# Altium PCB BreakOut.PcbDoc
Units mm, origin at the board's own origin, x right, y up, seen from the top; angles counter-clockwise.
Board outline 150 x 100 mm, 2 copper layers (Top Layer, Bottom Layer); 10 components, 137 nets, 339 pads, 72 vias.
Unrouted connection lines stored in the file: 1.
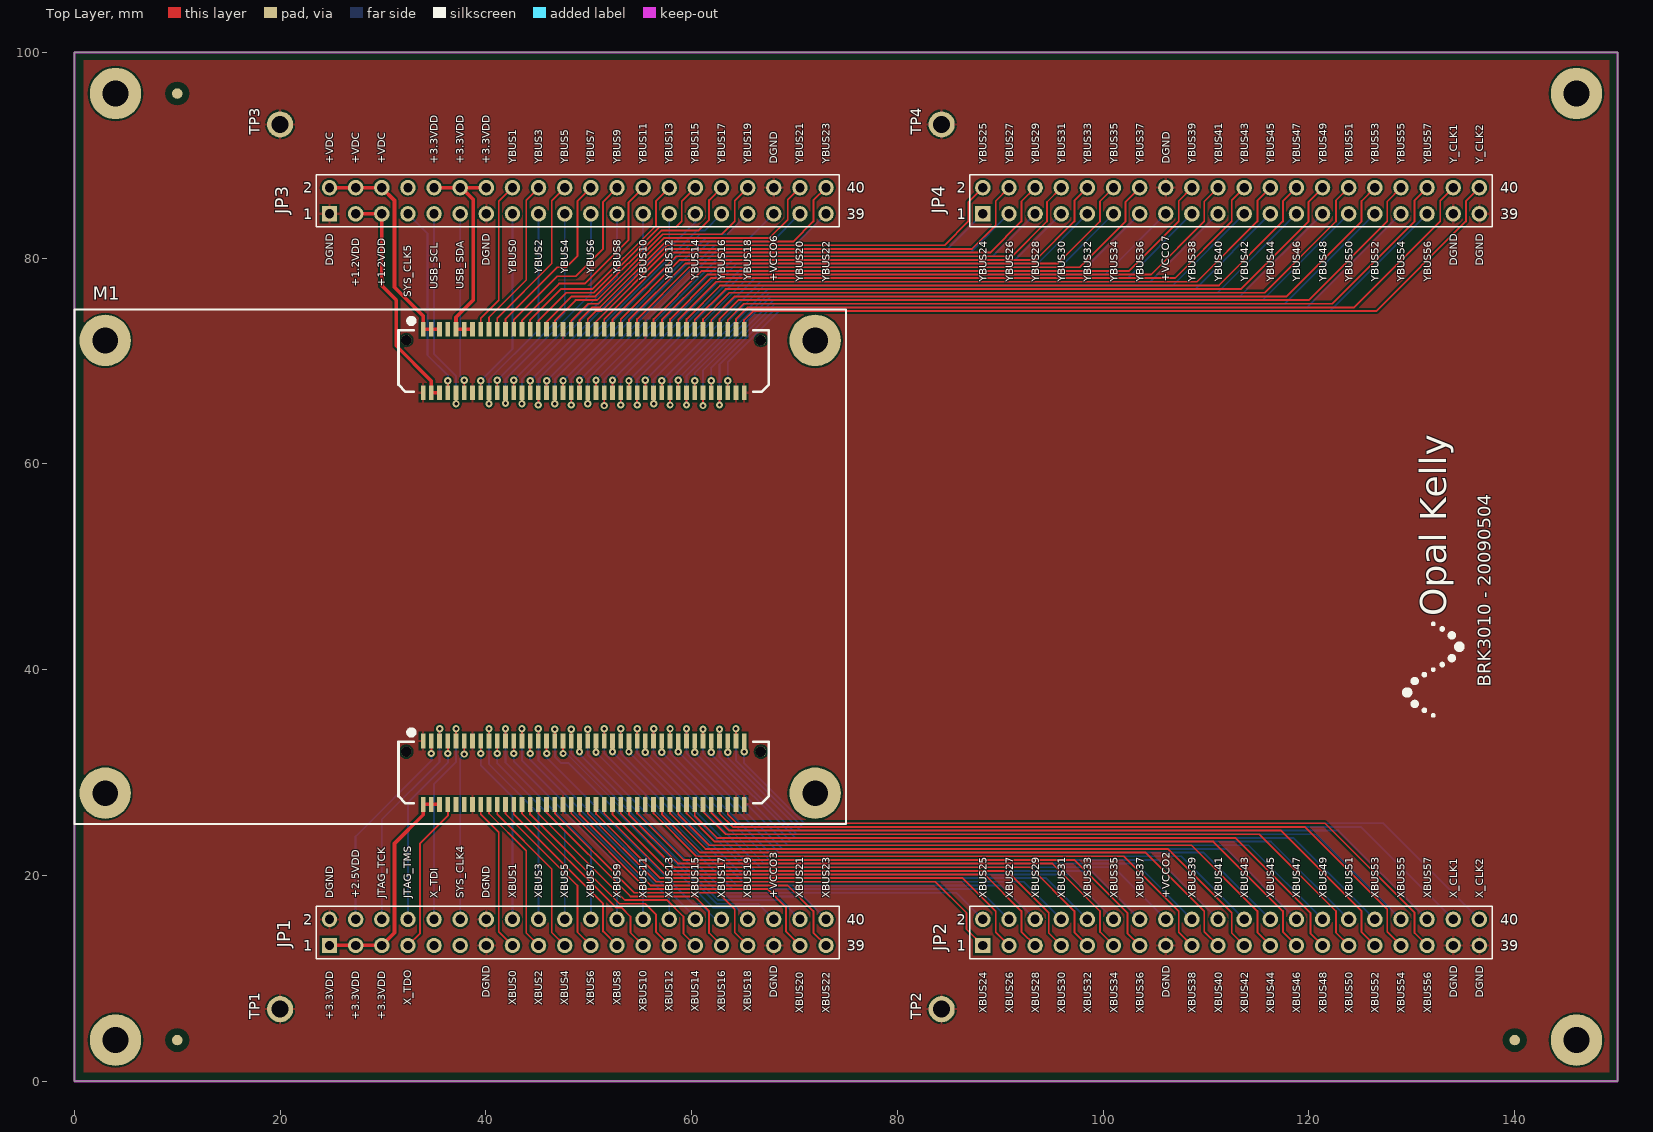
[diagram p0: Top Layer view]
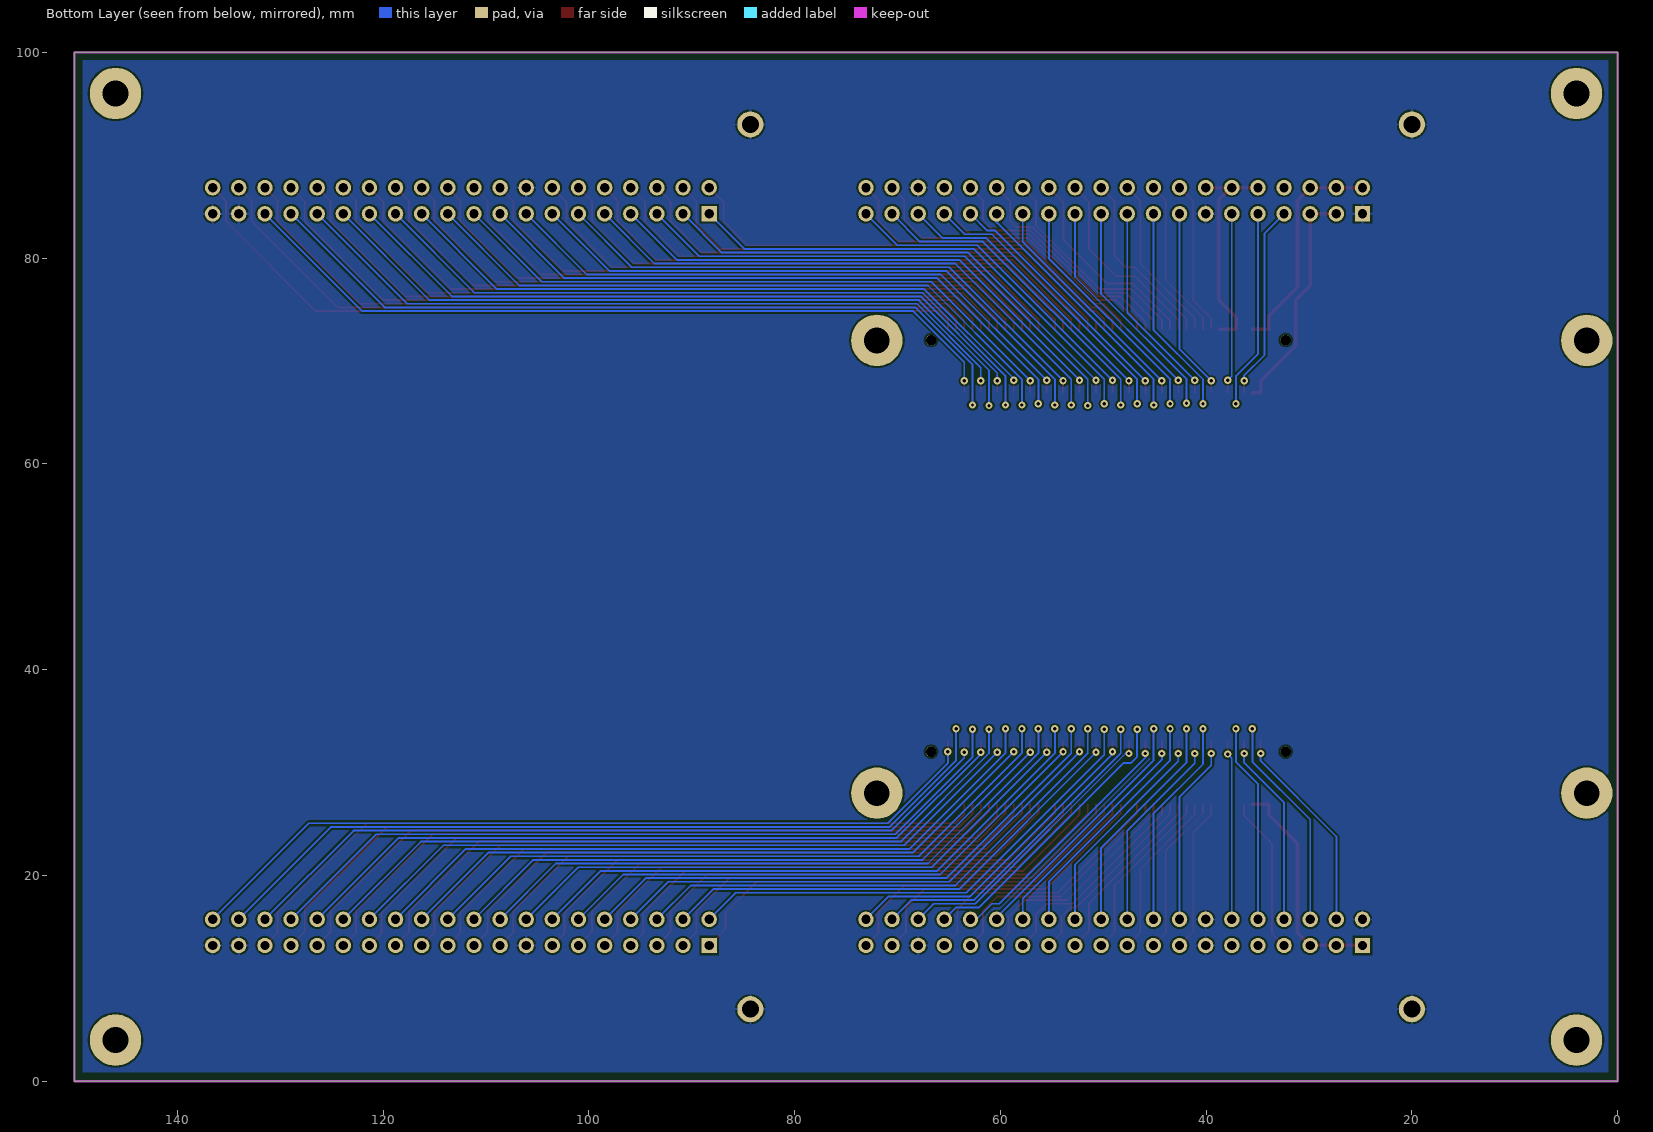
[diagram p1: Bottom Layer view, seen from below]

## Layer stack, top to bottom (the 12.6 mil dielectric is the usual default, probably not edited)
Top Layer: signal copper 0.0356
Dielectric: dielectric 0.32, FR-4, Dk 4.8
Bottom Layer: signal copper 0.0356

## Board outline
0,0 0,100 150,100 150,0

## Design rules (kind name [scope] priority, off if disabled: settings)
Clearance "Polygon Clearance" [InPolygon vs ((Not PadIsPlated) And (HoleSize = 0))] p1: gap=0.635
Clearance [All] p2: gap=0.178
FabricationTestPointUsage TestPointUsage [All] p1: valid=0 allowmultiple=FALSE
FabricationTestpoint Testpoint [All] p1: side=3 testpointundercomponent=TRUE minsize=1.016 maxsize=2.54 preferedsize=1.524 minholesize=0 maxholesize=1.016 preferedholesize=0.813 testpointgrid=0.025 allowsidetop=TRUE allowsidebottom=TRUE usegrid=TRUE gridtolerance=0
HoleSize [All] p1: absolutevalues=TRUE maxlimit=4.064 minlimit=0.33 maxpercent=80.000 minpercent=20.000
PolygonConnect [All] p1: connectstyle=Relief reliefconductorwidth=0.254 reliefentries=4 polygonreliefangle="90 Angle"
RoutingVias [All] p1: holewidth=0.33 width=0.711 viastyle="Through Hole" minholewidth=0.33 minwidth=0.711 maxholewidth=0.711 maxwidth=1.27
SilkscreenOverComponentPads [All] p1: minsilkscreentomaskgap=0.254
SolderMaskExpansion [All] p1: expansion=0.102
Width [All] p1: maxlimit=0.508 minlimit=0.178 preferedwidth=0.178 minimp=50.000000 maximp=50.000000 favimp=50.000000
24 further rules are at their usual default settings.

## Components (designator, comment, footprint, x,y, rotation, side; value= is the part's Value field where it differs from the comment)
JP1 "Header 20X2" HDR2X20 24.8,13.19 r0 top locked
JP2 "Header 20X2" HDR2X20 88.3,13.19 r0 top locked
JP3 "Header 20X2" HDR2X20 24.8,84.31 r0 top locked
JP4 "Header 20X2" HDR2X20 88.3,84.31 r0 top
M1 "XEM3010" XEM3010MODULE 0,25 r0 top locked
TP1 "TESTPOINT" TP_MED#1 20.32,10.668 r0 top
TP2 "TESTPOINT" TP_MED#2 81.072,8.128 r90 top
TP3 "TESTPOINT" TP_MED#3 17.78,93.472 r90 top
TP4 "TESTPOINT" TP_MED#4 81.072,93.472 r90 top
? "OKLOGO" oklogosmall 132.08,35.56 r90 top

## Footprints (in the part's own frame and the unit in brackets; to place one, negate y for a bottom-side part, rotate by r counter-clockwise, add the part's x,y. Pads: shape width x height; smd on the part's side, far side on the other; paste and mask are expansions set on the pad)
HDR2X20 [mm]
  rect 1.5x1.5 hole 0.9: 1(0,0)
  round 1.5 hole 0.9: 2(0,2.54) 3(2.54,0) 4(2.54,2.54) 5(5.08,0) 6(5.08,2.54) 7(7.62,0) 8(7.62,2.54) 9(10.16,0) 10(10.16,2.54) 11(12.7,0) 12(12.7,2.54) 13(15.24,0) 14(15.24,2.54) 15(17.78,0) 16(17.78,2.54) 17(20.32,0) 18(20.32,2.54) 19(22.86,0) 20(22.86,2.54) 21(25.4,0) 22(25.4,2.54) 23(27.94,0) 24(27.94,2.54) 25(30.48,0) 26(30.48,2.54) 27(33.02,0) 28(33.02,2.54) 29(35.56,0) 30(35.56,2.54) 31(38.1,0) 32(38.1,2.54) 33(40.64,0) 34(40.64,2.54) 35(43.18,0) 36(43.18,2.54) 37(45.72,0) 38(45.72,2.54) 39(48.26,0) 40(48.26,2.54)
  silkscreen extent -1.27,-1.27 49.53,3.81
oklogosmall [mm] "Opal Kelly silkscreen logo (100-mil)."
  silkscreen extent -0.11,-2.79 9,2.79
TP_MED#1 [mm] "Testpoint - medium sized"
  round 2.54 hole 1.651: 1(-0.32,-3.668)
TP_MED#2 [mm] "Testpoint - medium sized"
  round 2.54 hole 1.651: 1(-1.128,-3.228)
TP_MED#3 [mm] "Testpoint - medium sized"
  round 2.54 hole 1.651: 1(-0.472,-2.22)
TP_MED#4 [mm] "Testpoint - medium sized"
  round 2.54 hole 1.651: 1(-0.472,-3.228)
XEM3010MODULE [mm] "XEM3010 module footprint"
  round 5 hole 2.5: 0(3,3) 0(3,47) 0(72,3) 0(72,47)
  rect 0.46x1.45 smd: X1(33.9,8.085) X2(33.9,1.915) X3(34.7,8.085) X4(34.7,1.915) X5(35.5,8.085) X6(35.5,1.915) X7(36.3,8.085) X8(36.3,1.915) X9(37.1,8.085) X10(37.1,1.915) X11(37.9,8.085) X12(37.9,1.915) X13(38.7,8.085) X14(38.7,1.915) X15(39.5,8.085) X16(39.5,1.915) X17(40.3,8.085) X18(40.3,1.915) X19(41.1,8.085) X20(41.1,1.915) X21(41.9,8.085) X22(41.9,1.915) X23(42.7,8.085) X24(42.7,1.915) X25(43.5,8.085) X26(43.5,1.915) X27(44.3,8.085) X28(44.3,1.915) X29(45.1,8.085) X30(45.1,1.915) X31(45.9,8.085) X32(45.9,1.915) X33(46.7,8.085) X34(46.7,1.915) X35(47.5,8.085) X36(47.5,1.915) X37(48.3,8.085) X38(48.3,1.915) X39(49.1,8.085) X40(49.1,1.915) X41(49.9,8.085) X42(49.9,1.915) X43(50.7,8.085) X44(50.7,1.915) X45(51.5,8.085) X46(51.5,1.915) X47(52.3,8.085) X48(52.3,1.915) X49(53.1,8.085) X50(53.1,1.915) X51(53.9,8.085) X52(53.9,1.915) X53(54.7,8.085) X54(54.7,1.915) X55(55.5,8.085) X56(55.5,1.915) X57(56.3,8.085) X58(56.3,1.915) X59(57.1,8.085) X60(57.1,1.915) X61(57.9,8.085) X62(57.9,1.915) X63(58.7,8.085) X64(58.7,1.915) X65(59.5,8.085) X66(59.5,1.915) X67(60.3,8.085) X68(60.3,1.915) X69(61.1,8.085) X70(61.1,1.915) X71(61.9,8.085) X72(61.9,1.915) X73(62.7,8.085) X74(62.7,1.915) X75(63.5,8.085) X76(63.5,1.915) X77(64.3,8.085) X78(64.3,1.915) X79(65.1,8.085) X80(65.1,1.915) Y1(33.9,48.085) Y2(33.9,41.915) Y3(34.7,48.085) Y4(34.7,41.915) Y5(35.5,48.085) Y6(35.5,41.915) Y7(36.3,48.085) Y8(36.3,41.915) Y9(37.1,48.085) Y10(37.1,41.915) Y11(37.9,48.085) Y12(37.9,41.915) Y13(38.7,48.085) Y14(38.7,41.915) Y15(39.5,48.085) Y16(39.5,41.915) Y17(40.3,48.085) Y18(40.3,41.915) Y19(41.1,48.085) Y20(41.1,41.915) Y21(41.9,48.085) Y22(41.9,41.915) Y23(42.7,48.085) Y24(42.7,41.915) Y25(43.5,48.085) Y26(43.5,41.915) Y27(44.3,48.085) Y28(44.3,41.915) Y29(45.1,48.085) Y30(45.1,41.915) Y31(45.9,48.085) Y32(45.9,41.915) Y33(46.7,48.085) Y34(46.7,41.915) Y35(47.5,48.085) Y36(47.5,41.915) Y37(48.3,48.085) Y38(48.3,41.915) Y39(49.1,48.085) Y40(49.1,41.915) Y41(49.9,48.085) Y42(49.9,41.915) Y43(50.7,48.085) Y44(50.7,41.915) Y45(51.5,48.085) Y46(51.5,41.915) Y47(52.3,48.085) Y48(52.3,41.915) Y49(53.1,48.085) Y50(53.1,41.915) Y51(53.9,48.085) Y52(53.9,41.915) Y53(54.7,48.085) Y54(54.7,41.915) Y55(55.5,48.085) Y56(55.5,41.915) Y57(56.3,48.085) Y58(56.3,41.915) Y59(57.1,48.085) Y60(57.1,41.915) Y61(57.9,48.085) Y62(57.9,41.915) Y63(58.7,48.085) Y64(58.7,41.915) Y65(59.5,48.085) Y66(59.5,41.915) Y67(60.3,48.085) Y68(60.3,41.915) Y69(61.1,48.085) Y70(61.1,41.915) Y71(61.9,48.085) Y72(61.9,41.915) Y73(62.7,48.085) Y74(62.7,41.915) Y75(63.5,48.085) Y76(63.5,41.915) Y77(64.3,48.085) Y78(64.3,41.915) Y79(65.1,48.085) Y80(65.1,41.915)
  round 1.02 hole 1.02: X81(32.265,7.035) X82(66.735,7.035) Y81(32.265,47.035) Y82(66.735,47.035)
  silkscreen extent 0,0 75,50

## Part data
JP1 JP2 JP3 JP4: "Header, 20-Pin, Dual row"
M1: "XEM3010 module connectors"
TP1 TP2 TP3 TP4: "Testpoint"
?: "Opal Kelly PCB Logo"

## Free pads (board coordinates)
  round 5 hole 2.5: 0(4,4) 0(4,96) 0(146,4) 0(146,96)
  round 1.016 smd mask+0.508: FD0(10,96) FD1(10,4) FD2(140,4)

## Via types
v1: diameter 0.711, hole 0.33, Top Layer to Bottom Layer, tented both sides, 72 vias

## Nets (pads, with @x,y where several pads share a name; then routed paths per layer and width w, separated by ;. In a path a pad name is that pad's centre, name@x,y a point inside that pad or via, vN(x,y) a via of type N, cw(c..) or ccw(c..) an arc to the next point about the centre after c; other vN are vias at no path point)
+1.2VDD: JP3.3 JP3.5 M1.Y4 M1.Y6 | length 22.7
  Top Layer w0.356: JP3.3@27.34,84.3 29.88,84.3 29.88,77.333 31.293,75.921 31.293,71.476 34.7,68.068 M1.Y4 M1.Y6
+2.5VDD: JP1.4 M1.X3 | length 20.4
  Top Layer w0.178: v1(34.7,31.855) M1.X3
  Bottom Layer w0.178: JP1.4@27.34,15.74 27.34,23.784 34.7,31.144 v1(34.7,31.855)
+3.3VDD: JP1.1 JP1.3 JP1.5 JP3.10 JP3.12 JP3.14 M1.X2 M1.X4 M1.X6 M1.Y9 M1.Y11 M1.Y13 | length 43.7
  Top Layer w0.356: JP1.1@24.8,13.2 29.88,13.2 31.115,14.435 31.115,23.114 33.9,25.899 M1.X2 M1.X4 M1.X6 ; JP3.10@34.96,86.84 JP3.14@40.04,86.84 ; JP3.12@37.62,86.84 38.76,85.7 38.76,75.921 37.1,74.26 M1.Y9 M1.Y13
+VCCO2: JP2.16 M1.X55 | length 58.4
  Top Layer w0.178: v1(55.5,31.978) M1.X55
  Bottom Layer w0.178: v1(55.5,31.978) 66.675,20.803 101.017,20.803 JP2.16@106.08,15.74
+VCCO3: JP1.36 M1.X35 | length 28.4
  Top Layer w0.178: v1(47.5,31.854) M1.X35
  Bottom Layer w0.178: v1(47.5,31.854) 47.831,31.854 62.438,17.247 66.473,17.247 JP1.36@67.98,15.74
+VCCO6: JP3.35 M1.Y36 | length 28.4
  Top Layer w0.178: M1.Y36 v1(47.5,68.07)
  Bottom Layer w0.178: v1(47.5,68.07) 61.396,81.966 65.646,81.966 JP3.35@67.98,84.3
+VCCO7: JP4.15 M1.Y56 | length 58.5
  Top Layer w0.178: M1.Y56 v1(55.5,68.124)
  Bottom Layer w0.178: v1(55.5,68.124) 65.786,78.41 100.19,78.41 JP4.15@106.08,84.3
+VDC: JP3.2 JP3.4 JP3.6 M1.Y1 M1.Y3 M1.Y5 | length 22.1
  Top Layer w0.356: JP3.2@24.8,86.84 29.88,86.84 31.115,85.605 31.115,77.165 33.9,74.38 M1.Y1 M1.Y3 M1.Y5
DGND: JP1.2 JP1.13 JP1.14 JP1.35 JP2.15 JP2.37 JP2.39 JP3.1 JP3.13 JP3.36 JP4.16 JP4.37 JP4.39 M1.X1 M1.X13 M1.X14 M1.X36 M1.X56 M1.X78 M1.X80 M1.Y2 M1.Y14 M1.Y35 M1.Y55 M1.Y78 M1.Y80 TP1.1 TP2.1 TP3.1 TP4.1
JTAG_TCK: JP1.6 M1.X5 | length 22
  Top Layer w0.178: M1.X5 v1(35.5,34.255)
  Bottom Layer w0.178: JP1.6@29.88,15.74 29.88,25.435 35.5,31.055 v1(35.5,34.255)
JTAG_TMS: JP1.8 M1.X7 | length 19
  Top Layer w0.178: v1(36.3,31.855) M1.X7
  Bottom Layer w0.178: JP1.8@32.42,15.74 32.42,27.086 36.3,30.966 v1(36.3,31.855)
SYS_CLK4: JP1.12 M1.X11 | length 17.5
  Top Layer w0.178: v1(37.9,31.798) M1.X11
  Bottom Layer w0.178: JP1.12@37.5,15.74 37.5,31.398 v1(37.9,31.798)
SYS_CLK5: JP3.7 M1.Y8 | length 19
  Top Layer w0.178: M1.Y8 v1(36.3,68.069)
  Bottom Layer w0.178: JP3.7@32.42,84.3 34.315,82.405 34.315,70.587 36.3,68.602 v1(36.3,68.069)
USB_SCL: JP3.9 M1.Y10 | length 20.4
  Top Layer w0.178: v1(37.1,65.846) M1.Y10
  Bottom Layer w0.178: JP3.9@34.96,84.3 34.96,70.653 37.1,68.513 v1(37.1,65.846)
USB_SDA: JP3.11 M1.Y12 | length 17.6
  Top Layer w0.178: M1.Y12 v1(37.9,68.126)
  Bottom Layer w0.178: JP3.11@37.5,84.3 37.5,68.526 v1(37.9,68.126)
X_CLK1: JP2.38 M1.X77 | length 80.4
  Top Layer w0.178: M1.X77 v1(64.3,34.252)
  Bottom Layer w0.178: v1(64.3,34.252) 64.3,31.179 70.764,24.714 125.046,24.714 JP2.38@134.02,15.74
X_CLK2: JP2.40 M1.X79 | length 79.9
  Top Layer w0.178: v1(65.1,32.029) M1.X79
  Bottom Layer w0.178: v1(65.1,32.029) 65.1,30.912 70.942,25.07 127.23,25.07 JP2.40@136.56,15.74
X_TDI: JP1.10 M1.X9 | length 20.6
  Top Layer w0.178: M1.X9 v1(37.1,34.255)
  Bottom Layer w0.178: JP1.10@34.96,15.74 34.96,28.915 37.1,31.055 v1(37.1,34.255)
X_TDO: JP1.7 M1.X8 | length 15.3
  Top Layer w0.178: JP1.7@32.42,13.2 33.604,14.384 33.604,23.114 36.3,25.81 M1.X8
XBUS0: JP1.15 M1.X16 | length 15
  Top Layer w0.178: M1.X16 39.5,25.93 41.25,24.181 41.25,14.53 JP1.15@42.58,13.2
XBUS1: JP1.16 M1.X15 | length 18.6
  Top Layer w0.178: v1(39.5,31.855) M1.X15
  Bottom Layer w0.178: v1(39.5,31.855) 39.5,30.731 42.58,27.651 JP1.16@42.58,15.74
XBUS2: JP1.17 M1.X18 | length 15.7
  Top Layer w0.178: M1.X18 40.3,26.019 43.917,22.403 43.917,14.403 JP1.17@45.12,13.2
XBUS3: JP1.18 M1.X17 | length 21.7
  Top Layer w0.178: M1.X17 v1(40.3,34.255)
  Bottom Layer w0.178: v1(40.3,34.255) 40.3,30.82 45.12,26 JP1.18@45.12,15.74
XBUS4: JP1.19 M1.X20 | length 16.4
  Top Layer w0.178: M1.X20 41.1,25.931 46.406,20.625 46.406,14.454 JP1.19@47.66,13.2
XBUS5: JP1.20 M1.X19 | length 20.1
  Top Layer w0.178: v1(41.1,31.854) M1.X19
  Bottom Layer w0.178: v1(41.1,31.854) 41.1,30.909 47.66,24.349 JP1.20@47.66,15.74
XBUS6: JP1.21 M1.X22 | length 17.2
  Top Layer w0.178: M1.X22 41.9,26.02 48.895,19.025 48.895,14.505 JP1.21@50.2,13.2
XBUS7: JP1.22 M1.X21 | length 23.1
  Top Layer w0.178: M1.X21 v1(41.9,34.255)
  Bottom Layer w0.178: v1(41.9,34.255) 41.9,30.998 50.2,22.698 JP1.22@50.2,15.74
XBUS8: JP1.23 M1.X24 | length 17.9
  Top Layer w0.178: M1.X24 42.7,25.931 51.384,17.247 51.384,14.556 JP1.23@52.74,13.2
XBUS9: JP1.24 M1.X23 | length 21.5
  Top Layer w0.178: v1(42.7,31.854) M1.X23
  Bottom Layer w0.178: v1(42.7,31.854) 42.7,31.087 52.74,21.047 JP1.24@52.74,15.74
XBUS10: JP1.25 M1.X26 | length 18.9
  Top Layer w0.178: M1.X26 43.5,26.02 52.629,16.891 53.162,16.891 54.051,16.002 54.051,14.429 JP1.25@55.28,13.2
XBUS11: JP1.26 M1.X25 | length 24.6
  Top Layer w0.178: M1.X25 v1(43.5,34.254)
  Bottom Layer w0.178: v1(43.5,34.254) 43.5,31.176 55.28,19.396 JP1.26@55.28,15.74
XBUS12: JP1.27 M1.X28 | length 20.8
  Top Layer w0.178: M1.X28 44.3,25.931 52.984,17.247 55.474,17.247 56.54,16.18 56.54,14.48 JP1.27@57.82,13.2
XBUS13: JP1.28 M1.X27 | length 22.9
  Top Layer w0.178: v1(44.3,31.854) M1.X27
  Bottom Layer w0.178: v1(44.3,31.854) 44.3,31.265 57.82,17.745 JP1.28@57.82,15.74
XBUS14: JP1.29 M1.X30 | length 22.4
  Top Layer w0.178: M1.X30 45.1,26.02 53.518,17.602 57.607,17.602 59.207,16.002 59.207,14.353 JP1.29@60.36,13.2
XBUS15: JP1.30 M1.X29 | length 26
  Top Layer w0.178: M1.X29 v1(45.1,34.254)
  Bottom Layer w0.178: v1(45.1,34.254) 45.1,31.176 60.36,15.916 JP1.30@60.36,15.74
XBUS16: JP1.31 M1.X32 | length 24.4
  Top Layer w0.178: M1.X32 45.9,26.109 54.051,17.958 60.274,17.958 61.697,16.535 61.697,14.403 JP1.31@62.9,13.2
XBUS17: JP1.32 M1.X31 | length 25.1
  Top Layer w0.178: v1(45.9,31.854) M1.X31
  Bottom Layer w0.178: v1(45.9,31.854) 45.9,31.443 60.096,17.247 60.808,17.247 62.314,15.74 JP1.32@62.9,15.74
XBUS18: JP1.33 M1.X34 | length 26.3
  Top Layer w0.178: M1.X34 46.7,26.02 54.407,18.313 62.586,18.313 64.186,16.713 64.186,14.454 JP1.33@65.44,13.2
XBUS19: JP1.34 M1.X33 | length 29.1
  Top Layer w0.178: M1.X33 v1(46.7,34.199)
  Bottom Layer w0.178: v1(46.7,34.199) 46.7,31.532 47.295,30.937 48.006,30.937 62.052,16.891 64.289,16.891 JP1.34@65.44,15.74
XBUS20: JP1.37 M1.X38 | length 29.8
  Top Layer w0.178: M1.X38 48.3,26.02 55.651,18.669 67.386,18.669 69.164,16.891 69.164,14.556 JP1.37@70.52,13.2
XBUS21: JP1.38 M1.X37 | length 32.3
  Top Layer w0.178: M1.X37 v1(48.3,34.199)
  Bottom Layer w0.178: v1(48.3,34.199) 48.3,31.888 62.586,17.602 68.658,17.602 JP1.38@70.52,15.74
XBUS22: JP1.39 M1.X40 | length 31.5
  Top Layer w0.178: M1.X40 49.1,25.932 56.007,19.025 69.342,19.025 71.831,16.535 71.831,14.429 JP1.39@73.06,13.2
XBUS23: JP1.40 M1.X39 | length 31.9
  Top Layer w0.178: v1(49.1,32.031) M1.X39
  Bottom Layer w0.178: v1(49.1,32.031) 49.1,31.799 62.941,17.958 70.842,17.958 JP1.40@73.06,15.74
XBUS24: JP2.1 M1.X42 | length 45.5
  Top Layer w0.178: M1.X42 49.9,26.021 56.54,19.38 83.688,19.38 86.711,16.358 86.711,14.789 JP2.1@88.3,13.2
XBUS25: JP2.2 M1.X41 | length 48.6
  Top Layer w0.178: M1.X41 v1(49.9,34.199)
  Bottom Layer w0.178: v1(49.9,34.199) 49.9,31.71 63.297,18.313 85.727,18.313 JP2.2@88.3,15.74
XBUS26: JP2.3 M1.X44 | length 47.6
  Top Layer w0.178: M1.X44 50.7,25.986 56.95,19.736 86.355,19.736 89.556,16.535 89.556,14.484 JP2.3@90.84,13.2
XBUS27: JP2.4 M1.X43 | length 48
  Top Layer w0.178: v1(50.7,31.977) M1.X43
  Bottom Layer w0.178: v1(50.7,31.977) 64.008,18.669 87.911,18.669 JP2.4@90.84,15.74
XBUS28: JP2.5 M1.X46 | length 49.3
  Top Layer w0.178: M1.X46 51.5,26.021 57.429,20.091 88.489,20.091 92.045,16.535 92.045,14.535 JP2.5@93.38,13.2
XBUS29: JP2.6 M1.X45 | length 52.1
  Top Layer w0.178: M1.X45 v1(51.5,34.253)
  Bottom Layer w0.178: v1(51.5,34.253) 51.5,31.888 64.364,19.025 90.095,19.025 JP2.6@93.38,15.74
XBUS30: JP2.7 M1.X48 | length 51
  Top Layer w0.178: M1.X48 52.3,25.932 57.785,20.447 90.622,20.447 94.712,16.358 94.712,14.408 JP2.7@95.92,13.2
XBUS31: JP2.8 M1.X47 | length 51.4
  Top Layer w0.178: v1(52.3,32.031) M1.X47
  Bottom Layer w0.178: v1(52.3,32.031) 64.951,19.38 92.28,19.38 JP2.8@95.92,15.74
XBUS32: JP2.9 M1.X50 | length 52.8
  Top Layer w0.178: M1.X50 53.1,26.021 58.318,20.803 92.934,20.803 97.201,16.535 97.201,14.459 JP2.9@98.46,13.2
XBUS33: JP2.10 M1.X49 | length 55.6
  Top Layer w0.178: M1.X49 v1(53.1,34.253)
  Bottom Layer w0.178: v1(53.1,34.253) 53.1,31.888 65.253,19.736 94.464,19.736 JP2.10@98.46,15.74
XBUS34: JP2.11 M1.X52 | length 54.5
  Top Layer w0.178: M1.X52 53.9,25.932 58.674,21.158 95.067,21.158 99.69,16.535 99.69,14.51 JP2.11@101,13.2
XBUS35: JP2.12 M1.X51 | length 54.9
  Top Layer w0.178: v1(53.9,32.031) M1.X51
  Bottom Layer w0.178: v1(53.9,32.031) 65.839,20.091 96.649,20.091 JP2.12@101,15.74
XBUS36: JP2.13 M1.X54 | length 56.2
  Top Layer w0.178: M1.X54 54.7,26.021 59.207,21.514 97.201,21.514 102.357,16.358 102.357,14.383 JP2.13@103.54,13.2
XBUS37: JP2.14 M1.X53 | length 59.1
  Top Layer w0.178: M1.X53 v1(54.7,34.253)
  Bottom Layer w0.178: v1(54.7,34.253) 54.7,31.889 66.142,20.447 98.833,20.447 JP2.14@103.54,15.74
XBUS38: JP2.17 M1.X58 | length 59.7
  Top Layer w0.178: M1.X58 56.3,26.021 60.452,21.869 102.002,21.869 107.336,16.535 107.336,14.484 JP2.17@108.62,13.2
XBUS39: JP2.18 M1.X57 | length 62.5
  Top Layer w0.178: M1.X57 v1(56.3,34.253)
  Bottom Layer w0.178: v1(56.3,34.253) 56.3,31.889 67.031,21.158 103.202,21.158 JP2.18@108.62,15.74
XBUS40: JP2.19 M1.X60 | length 61.5
  Top Layer w0.178: M1.X60 57.1,25.933 60.808,22.225 104.135,22.225 109.825,16.535 109.825,14.535 JP2.19@111.16,13.2
XBUS41: JP2.20 M1.X59 | length 61.9
  Top Layer w0.178: v1(57.1,31.978) M1.X59
  Bottom Layer w0.178: v1(57.1,31.978) 67.564,21.514 105.386,21.514 JP2.20@111.16,15.74
XBUS42: JP2.21 M1.X62 | length 63.1
  Top Layer w0.178: M1.X62 57.9,26.022 61.341,22.581 106.269,22.581 112.492,16.358 112.492,14.408 JP2.21@113.7,13.2
XBUS43: JP2.22 M1.X61 | length 66
  Top Layer w0.178: M1.X61 v1(57.9,34.253)
  Bottom Layer w0.178: v1(57.9,34.253) 57.9,31.889 67.92,21.869 107.571,21.869 JP2.22@113.7,15.74
XBUS44: JP2.23 M1.X64 | length 65
  Top Layer w0.178: M1.X64 58.7,25.933 61.697,22.936 108.58,22.936 114.981,16.535 114.981,14.459 JP2.23@116.24,13.2
XBUS45: JP2.24 M1.X63 | length 65.3
  Top Layer w0.178: v1(58.7,32.03) M1.X63
  Bottom Layer w0.178: v1(58.7,32.03) 68.505,22.225 109.755,22.225 JP2.24@116.24,15.74
XBUS46: JP2.25 M1.X66 | length 66.7
  Top Layer w0.178: M1.X66 59.5,26.022 62.23,23.292 110.714,23.292 117.47,16.535 117.47,14.51 JP2.25@118.78,13.2
XBUS47: JP2.26 M1.X65 | length 69.5
  Top Layer w0.178: M1.X65 v1(59.5,34.252)
  Bottom Layer w0.178: v1(59.5,34.252) 59.5,31.889 68.809,22.581 111.939,22.581 JP2.26@118.78,15.74
XBUS48: JP2.27 M1.X68 | length 68.5
  Top Layer w0.178: M1.X68 60.3,25.807 62.459,23.647 112.847,23.647 120.137,16.358 120.137,14.383 JP2.27@121.32,13.2
XBUS49: JP2.28 M1.X67 | length 68.9
  Top Layer w0.178: v1(60.3,31.978) M1.X67
  Bottom Layer w0.178: v1(60.3,31.978) 69.342,22.936 114.124,22.936 JP2.28@121.32,15.74
XBUS50: JP2.29 M1.X70 | length 70.1
  Top Layer w0.178: M1.X70 61.1,26.2 63.297,24.003 115.159,24.003 122.626,16.535 122.626,14.434 JP2.29@123.86,13.2
XBUS51: JP2.30 M1.X69 | length 72.9
  Top Layer w0.178: M1.X69 v1(61.1,34.201)
  Bottom Layer w0.178: v1(61.1,34.201) 61.1,31.889 69.698,23.292 116.308,23.292 JP2.30@123.86,15.74
XBUS52: JP2.31 M1.X72 | length 71.9
  Top Layer w0.178: M1.X72 61.9,26.111 63.652,24.359 117.292,24.359 125.116,16.535 125.116,14.484 JP2.31@126.4,13.2
XBUS53: JP2.32 M1.X71 | length 72.4
  Top Layer w0.178: v1(61.9,31.978) M1.X71
  Bottom Layer w0.178: v1(61.9,31.978) 61.9,31.801 70.053,23.647 118.493,23.647 JP2.32@126.4,15.74
XBUS54: JP2.33 M1.X74 | length 73.7
  Top Layer w0.178: M1.X74 62.7,26.022 64.008,24.714 119.604,24.714 127.605,16.713 127.605,14.535 JP2.33@128.94,13.2
XBUS55: JP2.34 M1.X73 | length 76.6
  Top Layer w0.178: M1.X73 v1(62.7,34.201)
  Bottom Layer w0.178: v1(62.7,34.201) 62.7,31.534 70.231,24.003 120.677,24.003 JP2.34@128.94,15.74
XBUS56: JP2.35 M1.X76 | length 75.4
  Top Layer w0.178: M1.X76 63.5,25.933 64.364,25.07 121.56,25.07 130.272,16.358 130.272,14.408 JP2.35@131.48,13.2
XBUS57: JP2.36 M1.X75 | length 76.1
  Top Layer w0.178: v1(63.5,31.979) M1.X75
  Bottom Layer w0.178: v1(63.5,31.979) 63.5,31.445 70.587,24.359 122.861,24.359 JP2.36@131.48,15.74
Y_CLK1: JP4.38 M1.Y77 | length 77.2
  Top Layer w0.178: M1.Y77 64.3,74.079 65.43,75.209 124.404,75.209 132.761,83.566 132.761,85.581 JP4.38@134.02,86.84
Y_CLK2: JP4.40 M1.Y79 | length 78.8
  Top Layer w0.178: M1.Y79 65.1,73.99 65.964,74.854 126.538,74.854 135.25,83.566 135.25,85.522 136.56,86.832 JP4.40@136.56,86.84
YBUS0: JP3.15 M1.Y16 | length 18.7
  Top Layer w0.178: M1.Y16 v1(39.5,68.069)
  Bottom Layer w0.178: v1(39.5,68.069) 42.58,71.149 JP3.15@42.58,84.3
YBUS1: JP3.16 M1.Y15 | length 15
  Top Layer w0.178: M1.Y15 39.5,74.171 41.25,75.921 41.25,85.51 JP3.16@42.58,86.84
YBUS2: JP3.17 M1.Y18 | length 21.5
  Top Layer w0.178: v1(40.3,65.847) M1.Y18
  Bottom Layer w0.178: v1(40.3,65.847) 40.3,68.215 45.12,73.035 JP3.17@45.12,84.3
YBUS3: JP3.18 M1.Y17 | length 15.8
  Top Layer w0.178: M1.Y17 40.3,74.26 43.917,77.876 43.917,85.637 JP3.18@45.12,86.84
YBUS4: JP3.19 M1.Y20 | length 20.1
  Top Layer w0.178: M1.Y20 v1(41.1,68.126)
  Bottom Layer w0.178: v1(41.1,68.126) 47.66,74.686 JP3.19@47.66,84.3
YBUS5: JP3.20 M1.Y19 | length 16.5
  Top Layer w0.178: M1.Y19 41.1,74.171 46.406,79.477 46.406,85.586 JP3.20@47.66,86.84
YBUS6: JP3.21 M1.Y22 | length 22.8
  Top Layer w0.178: v1(41.9,65.903) M1.Y22
  Bottom Layer w0.178: v1(41.9,65.903) 41.9,68.214 50.2,76.514 JP3.21@50.2,84.3
YBUS7: JP3.22 M1.Y21 | length 17.7
  Top Layer w0.178: M1.Y21 41.9,74.082 46.939,79.121 47.828,79.121 48.895,80.188 48.895,85.535 JP3.22@50.2,86.84
YBUS8: JP3.23 M1.Y24 | length 21.5
  Top Layer w0.178: M1.Y24 v1(42.7,68.125)
  Bottom Layer w0.178: v1(42.7,68.125) 52.74,78.165 JP3.23@52.74,84.3
YBUS9: JP3.24 M1.Y23 | length 19
  Top Layer w0.178: M1.Y23 42.7,73.993 46.939,78.232 48.717,78.232 51.384,80.899 51.384,85.484 JP3.24@52.74,86.84
YBUS10: JP3.25 M1.Y26 | length 24.4
  Top Layer w0.178: v1(43.5,65.847) M1.Y26
  Bottom Layer w0.178: v1(43.5,65.847) 43.5,68.214 55.28,79.994 JP3.25@55.28,84.3
YBUS11: JP3.26 M1.Y25 | length 20.1
  Top Layer w0.178: M1.Y25 43.5,73.904 47.117,77.521 49.606,77.521 53.873,81.788 53.873,85.433 JP3.26@55.28,86.84
YBUS12: JP3.27 M1.Y28 | length 23
  Top Layer w0.178: M1.Y28 v1(44.3,68.07)
  Bottom Layer w0.178: v1(44.3,68.07) 57.82,81.59 JP3.27@57.82,84.3
YBUS13: JP3.28 M1.Y27 | length 21.1
  Top Layer w0.178: M1.Y27 44.3,73.993 47.295,76.987 50.353,76.987 56.54,83.175 56.54,85.56 JP3.28@57.82,86.84
YBUS14: JP3.29 M1.Y30 | length 26.1
  Top Layer w0.178: v1(45.1,65.725) M1.Y30
  Bottom Layer w0.178: v1(45.1,65.725) 45.1,68.214 60.36,83.474 JP3.29@60.36,84.3
YBUS15: JP3.30 M1.Y29 | length 22.6
  Top Layer w0.178: M1.Y29 45.1,73.904 47.828,76.632 50.5,76.632 56.901,83.033 58.496,83.033 59.03,83.566 59.03,85.51 JP3.30@60.36,86.84
YBUS16: JP3.31 M1.Y32 | length 24.9
  Top Layer w0.178: M1.Y32 v1(45.9,68.07)
  Bottom Layer w0.178: v1(45.9,68.07) 60.507,82.677 61.277,82.677 JP3.31@62.9,84.3
YBUS17: JP3.32 M1.Y31 | length 24.2
  Top Layer w0.178: M1.Y31 45.9,73.815 48.362,76.276 50.648,76.276 57.049,82.677 60.63,82.677 61.697,83.744 61.697,85.637 JP3.32@62.9,86.84
YBUS18: JP3.33 M1.Y34 | length 28.8
  Top Layer w0.178: v1(46.7,65.847) M1.Y34
  Bottom Layer w0.178: v1(46.7,65.847) 46.7,68.214 60.808,82.321 63.461,82.321 JP3.33@65.44,84.3
YBUS19: JP3.34 M1.Y33 | length 26.1
  Top Layer w0.178: M1.Y33 46.7,73.903 48.717,75.921 50.795,75.921 57.196,82.321 62.941,82.321 64.186,83.566 64.186,85.586 JP3.34@65.44,86.84
YBUS20: JP3.37 M1.Y38 | length 32.6
  Top Layer w0.178: v1(48.3,65.724) M1.Y38
  Bottom Layer w0.178: v1(48.3,65.724) 48.3,68.214 61.697,81.61 67.83,81.61 JP3.37@70.52,84.3
YBUS21: JP3.38 M1.Y37 | length 29.5
  Top Layer w0.178: M1.Y37 48.3,73.903 49.962,75.565 50.942,75.565 57.343,81.966 67.564,81.966 69.342,83.744 69.342,85.662 JP3.38@70.52,86.84
YBUS22: JP3.39 M1.Y40 | length 31.9
  Top Layer w0.178: M1.Y40 v1(49.1,68.125)
  Bottom Layer w0.178: v1(49.1,68.125) 62.23,81.255 70.015,81.255 JP3.39@73.06,84.3
YBUS23: JP3.40 M1.Y39 | length 31.4
  Top Layer w0.178: M1.Y39 49.1,73.992 50.317,75.209 51.09,75.209 57.49,81.61 69.875,81.61 71.831,83.566 71.831,85.611 JP3.40@73.06,86.84
YBUS24: JP4.1 M1.Y42 | length 48.5
  Top Layer w0.178: v1(49.9,65.848) M1.Y42
  Bottom Layer w0.178: v1(49.9,65.848) 49.9,68.213 62.586,80.899 84.899,80.899 JP4.1@88.3,84.3
YBUS25: JP4.2 M1.Y41 | length 45.8
  Top Layer w0.178: M1.Y41 49.9,74.081 50.673,74.854 51.237,74.854 57.638,81.255 84.577,81.255 86.889,83.566 86.889,85.429 JP4.2@88.3,86.84
YBUS26: JP4.3 M1.Y44 | length 48
  Top Layer w0.178: M1.Y44 v1(50.7,68.124)
  Bottom Layer w0.178: v1(50.7,68.124) 63.119,80.543 87.083,80.543 JP4.3@90.84,84.3
YBUS27: JP4.4 M1.Y43 | length 47.6
  Top Layer w0.178: M1.Y43 50.7,73.814 57.785,80.899 87.244,80.899 89.556,83.21 89.556,85.556 JP4.4@90.84,86.84
YBUS28: JP4.5 M1.Y46 | length 52.3
  Top Layer w0.178: v1(51.5,65.67) M1.Y46
  Bottom Layer w0.178: v1(51.5,65.67) 51.5,68.213 63.475,80.188 89.268,80.188 JP4.5@93.38,84.3
YBUS29: JP4.6 M1.Y45 | length 49.3
  Top Layer w0.178: M1.Y45 51.5,74.081 57.963,80.543 89.022,80.543 92.045,83.566 92.045,85.505 JP4.6@93.38,86.84
YBUS30: JP4.7 M1.Y48 | length 51.5
  Top Layer w0.178: M1.Y48 v1(52.3,68.124)
  Bottom Layer w0.178: v1(52.3,68.124) 64.008,79.832 91.452,79.832 JP4.7@95.92,84.3
YBUS31: JP4.8 M1.Y47 | length 51
  Top Layer w0.178: M1.Y47 52.3,73.992 58.496,80.188 91.156,80.188 94.534,83.566 94.534,85.454 JP4.8@95.92,86.84
YBUS32: JP4.9 M1.Y50 | length 55.7
  Top Layer w0.178: v1(53.1,65.724) M1.Y50
  Bottom Layer w0.178: v1(53.1,65.724) 53.1,68.213 64.364,79.477 93.637,79.477 JP4.9@98.46,84.3
YBUS33: JP4.10 M1.Y49 | length 52.8
  Top Layer w0.178: M1.Y49 53.1,74.08 58.852,79.832 93.467,79.832 97.201,83.566 97.201,85.581 JP4.10@98.46,86.84
YBUS34: JP4.11 M1.Y52 | length 55
  Top Layer w0.178: M1.Y52 v1(53.9,68.071)
  Bottom Layer w0.178: v1(53.9,68.071) 64.95,79.121 95.821,79.121 JP4.11@101,84.3
YBUS35: JP4.12 M1.Y51 | length 54.5
  Top Layer w0.178: M1.Y51 53.9,73.991 59.385,79.477 95.601,79.477 99.69,83.566 99.69,85.53 JP4.12@101,86.84
YBUS36: JP4.13 M1.Y54 | length 59.2
  Top Layer w0.178: v1(54.7,65.724) M1.Y54
  Bottom Layer w0.178: v1(54.7,65.724) 54.7,68.213 65.253,78.765 98.005,78.765 JP4.13@103.54,84.3
YBUS37: JP4.14 M1.Y53 | length 56.2
  Top Layer w0.178: M1.Y53 54.7,74.08 59.741,79.121 97.734,79.121 102.179,83.566 102.179,85.479 JP4.14@103.54,86.84
YBUS38: JP4.17 M1.Y58 | length 62.4
  Top Layer w0.178: v1(56.3,65.849) M1.Y58
  Bottom Layer w0.178: v1(56.3,65.849) 56.3,68.213 66.142,78.054 102.374,78.054 JP4.17@108.62,84.3
YBUS39: JP4.18 M1.Y57 | length 59.8
  Top Layer w0.178: M1.Y57 56.3,74.08 60.985,78.765 102.535,78.765 107.336,83.566 107.336,85.556 JP4.18@108.62,86.84
YBUS40: JP4.19 M1.Y60 | length 61.9
  Top Layer w0.178: M1.Y60 v1(57.1,68.071)
  Bottom Layer w0.178: v1(57.1,68.071) 66.727,77.699 104.559,77.699 JP4.19@111.16,84.3
YBUS41: JP4.20 M1.Y59 | length 61.4
  Top Layer w0.178: M1.Y59 57.1,73.991 61.519,78.41 104.669,78.41 109.825,83.566 109.825,85.505 JP4.20@111.16,86.84
YBUS42: JP4.21 M1.Y62 | length 66.1
  Top Layer w0.178: v1(57.9,65.723) M1.Y62
  Bottom Layer w0.178: v1(57.9,65.723) 57.9,68.212 67.031,77.343 106.743,77.343 JP4.21@113.7,84.3
YBUS43: JP4.22 M1.Y61 | length 63.3
  Top Layer w0.178: M1.Y61 57.9,74.08 61.874,78.054 106.98,78.054 112.492,83.566 112.492,85.632 JP4.22@113.7,86.84
YBUS44: JP4.23 M1.Y64 | length 65.6
  Top Layer w0.178: M1.Y64 v1(58.7,68.123)
  Bottom Layer w0.178: v1(58.7,68.123) 58.7,68.301 67.386,76.987 108.927,76.987 JP4.23@116.24,84.3
YBUS45: JP4.24 M1.Y63 | length 64.9
  Top Layer w0.178: M1.Y63 58.7,73.991 62.408,77.699 109.114,77.699 114.981,83.566 114.981,85.581 JP4.24@116.24,86.84
YBUS46: JP4.25 M1.Y66 | length 69.8
  Top Layer w0.178: v1(59.5,65.723) M1.Y66
  Bottom Layer w0.178: v1(59.5,65.723) 59.5,68.568 67.564,76.632 111.112,76.632 JP4.25@118.78,84.3
YBUS47: JP4.26 M1.Y65 | length 66.7
  Top Layer w0.178: M1.Y65 59.5,74.08 62.763,77.343 111.247,77.343 117.47,83.566 117.47,85.53 JP4.26@118.78,86.84
YBUS48: JP4.27 M1.Y68 | length 69.3
  Top Layer w0.178: M1.Y68 v1(60.3,68.072)
  Bottom Layer w0.178: v1(60.3,68.072) 60.3,68.834 67.742,76.276 113.296,76.276 JP4.27@121.32,84.3
YBUS49: JP4.28 M1.Y67 | length 68.4
  Top Layer w0.178: M1.Y67 60.3,73.991 63.297,76.987 113.381,76.987 119.959,83.566 119.959,85.479 JP4.28@121.32,86.84
YBUS50: JP4.29 M1.Y70 | length 73.7
  Top Layer w0.178: v1(61.1,65.671) M1.Y70
  Bottom Layer w0.178: v1(61.1,65.671) 61.1,69.101 67.92,75.921 115.481,75.921 JP4.29@123.86,84.3
YBUS51: JP4.30 M1.Y69 | length 70.2
  Top Layer w0.178: M1.Y69 61.1,74.079 63.652,76.632 115.692,76.632 122.626,83.566 122.626,85.606 JP4.30@123.86,86.84
YBUS52: JP4.31 M1.Y72 | length 73.1
  Top Layer w0.178: M1.Y72 v1(61.9,68.072)
  Bottom Layer w0.178: v1(61.9,68.072) 61.9,69.368 68.097,75.565 117.665,75.565 JP4.31@126.4,84.3
YBUS53: JP4.32 M1.Y71 | length 71.9
  Top Layer w0.178: M1.Y71 61.9,73.99 64.186,76.276 117.826,76.276 125.116,83.566 125.116,85.556 JP4.32@126.4,86.84
YBUS54: JP4.33 M1.Y74 | length 77.4
  Top Layer w0.178: v1(62.7,65.723) M1.Y74
  Bottom Layer w0.178: v1(62.7,65.723) 62.7,69.634 68.275,75.209 119.849,75.209 JP4.33@128.94,84.3
YBUS55: JP4.34 M1.Y73 | length 73.7
  Top Layer w0.178: M1.Y73 62.7,74.079 64.541,75.921 119.959,75.921 127.605,83.566 127.605,85.505 JP4.34@128.94,86.84
YBUS56: JP4.35 M1.Y76 | length 76.9
  Top Layer w0.178: M1.Y76 v1(63.5,68.072)
  Bottom Layer w0.178: v1(63.5,68.072) 63.5,69.901 68.453,74.854 122.034,74.854 JP4.35@131.48,84.3
YBUS57: JP4.36 M1.Y75 | length 75.4
  Top Layer w0.178: M1.Y75 63.5,73.99 65.075,75.565 122.271,75.565 130.272,83.566 130.272,85.632 JP4.36@131.48,86.84
pads on no net: JP1.9 JP1.11 JP3.8 M1.0 M1.X10 M1.X12 M1.X81 M1.X82 M1.Y7 M1.Y81 M1.Y82

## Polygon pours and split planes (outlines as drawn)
DGND on Top Layer "Top Layer-DGND" (solid, remove dead copper, pour order 1000): 0.889,0.889 149.174,0.889 149.174,99.212 0.889,99.212
DGND on Bottom Layer "Bot Layer-DGND" (solid, remove dead copper, pour order 1000): 0.889,0.889 149.174,0.889 149.174,99.212 0.889,99.212

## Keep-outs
Keep-Out Layer:
  the board outline again, w0.203

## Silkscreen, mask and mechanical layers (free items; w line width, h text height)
Top Overlay:
  text "+VDC" at 25.146,89.154 h0.76 r90
  text "+VDC" at 27.686,89.154 h0.76 r90
  text "+VDC" at 30.226,89.154 h0.76 r90
  text "+3.3VDD" at 35.306,89.154 h0.76 r90
  text "+3.3VDD" at 37.846,89.154 h0.76 r90
  text "+3.3VDD" at 40.386,89.154 h0.76 r90
  text "YBUS1" at 42.926,89.154 h0.76 r90
  text "YBUS3" at 45.466,89.154 h0.76 r90
  text "YBUS5" at 48.006,89.154 h0.76 r90
  text "YBUS7" at 50.546,89.154 h0.76 r90
  text "YBUS9" at 53.086,89.154 h0.76 r90
  text "YBUS11" at 55.626,89.154 h0.76 r90
  text "YBUS13" at 58.166,89.154 h0.76 r90
  text "YBUS15" at 60.706,89.154 h0.76 r90
  text "YBUS17" at 63.246,89.154 h0.76 r90
  text "YBUS19" at 65.786,89.154 h0.76 r90
  text "DGND" at 68.326,89.154 h0.76 r90
  text "YBUS21" at 70.866,89.154 h0.76 r90
  text "YBUS23" at 73.406,89.154 h0.76 r90
  text "YBUS25" at 88.692,89.154 h0.76 r90
  text "YBUS27" at 91.232,89.154 h0.76 r90
  text "YBUS29" at 93.772,89.154 h0.76 r90
  text "YBUS31" at 96.312,89.154 h0.76 r90
  text "YBUS33" at 98.852,89.154 h0.76 r90
  text "YBUS35" at 101.392,89.154 h0.76 r90
  text "YBUS37" at 103.932,89.154 h0.76 r90
  text "DGND" at 106.472,89.154 h0.76 r90
  text "YBUS39" at 109.012,89.154 h0.76 r90
  text "YBUS41" at 111.552,89.154 h0.76 r90
  text "YBUS43" at 114.092,89.154 h0.76 r90
  text "YBUS45" at 116.632,89.154 h0.76 r90
  text "YBUS47" at 119.172,89.154 h0.76 r90
  text "YBUS49" at 121.712,89.154 h0.76 r90
  text "YBUS51" at 124.252,89.154 h0.76 r90
  text "YBUS53" at 126.792,89.154 h0.76 r90
  text "YBUS55" at 129.332,89.154 h0.76 r90
  text "YBUS57" at 131.872,89.154 h0.76 r90
  text "Y_CLK1" at 134.412,89.154 h0.76 r90
  text "Y_CLK2" at 136.952,89.154 h0.76 r90
  text "DGND" at 25.146,79.247 h0.76 r90
  text "DGND" at 40.386,79.247 h0.76 r90
  text "DGND" at 134.412,79.247 h0.76 r90
  text "DGND" at 136.952,79.247 h0.76 r90
  text "YBUS0" at 42.926,78.486 h0.76 r90
  text "YBUS2" at 45.466,78.486 h0.76 r90
  text "YBUS4" at 48.006,78.486 h0.76 r90
  text "YBUS6" at 50.546,78.486 h0.76 r90
  text "YBUS8" at 53.086,78.486 h0.76 r90
  text "YBUS10" at 55.626,77.851 h0.76 r90
  text "YBUS12" at 58.166,77.851 h0.76 r90
  text "YBUS14" at 60.706,77.851 h0.76 r90
  text "YBUS16" at 63.246,77.851 h0.76 r90
  text "YBUS18" at 65.786,77.851 h0.76 r90
  text "YBUS20" at 70.866,77.724 h0.76 r90
  text "YBUS22" at 73.406,77.724 h0.76 r90
  text "YBUS24" at 88.692,77.724 h0.76 r90
  text "YBUS26" at 91.232,77.724 h0.76 r90
  text "YBUS28" at 93.772,77.724 h0.76 r90
  text "YBUS30" at 96.312,77.724 h0.76 r90
  text "YBUS32" at 98.852,77.724 h0.76 r90
  text "YBUS34" at 101.392,77.724 h0.76 r90
  text "YBUS36" at 103.932,77.724 h0.76 r90
  text "+VCCO7" at 106.426,77.724 h0.76 r90
  text "YBUS38" at 109.012,77.724 h0.76 r90
  text "YBUS40" at 111.552,77.724 h0.76 r90
  text "YBUS42" at 114.092,77.724 h0.76 r90
  text "YBUS44" at 116.632,77.724 h0.76 r90
  text "YBUS46" at 119.172,77.724 h0.76 r90
  text "YBUS48" at 121.712,77.724 h0.76 r90
  text "YBUS50" at 124.252,77.724 h0.76 r90
  text "YBUS52" at 126.792,77.724 h0.76 r90
  text "YBUS54" at 129.332,77.724 h0.76 r90
  text "YBUS56" at 131.872,77.724 h0.76 r90
  text "+VCCO6" at 68.326,77.699 h0.76 r90
  text "+1.2VDD" at 27.686,77.216 h0.76 r90
  text "+1.2VDD" at 30.226,77.216 h0.76 r90
  text "USB_SCL" at 35.306,76.962 h0.76 r90
  text "USB_SDA" at 37.846,76.962 h0.76 r90
  text "SYS_CLK5" at 32.766,76.2 h0.76 r90
  text "BRK3010 - 20090504" at 137.668,38.354 h1.27 r90
  text "DGND" at 25.146,17.78 h0.76 r90
  text "+2.5VDD" at 27.686,17.78 h0.76 r90
  text "JTAG_TCK" at 30.226,17.78 h0.76 r90
  text "JTAG_TMS" at 32.766,17.78 h0.76 r90
  text "X_TDI" at 35.306,17.78 h0.76 r90
  text "SYS_CLK4" at 37.846,17.78 h0.76 r90
  text "DGND" at 40.386,17.78 h0.76 r90
  text "XBUS1" at 42.926,17.78 h0.76 r90
  text "XBUS3" at 45.466,17.78 h0.76 r90
  text "XBUS5" at 48.006,17.78 h0.76 r90
  text "XBUS7" at 50.546,17.78 h0.76 r90
  text "XBUS9" at 53.086,17.78 h0.76 r90
  text "XBUS11" at 55.626,17.78 h0.76 r90
  text "XBUS13" at 58.166,17.78 h0.76 r90
  text "XBUS15" at 60.706,17.78 h0.76 r90
  text "XBUS17" at 63.246,17.78 h0.76 r90
  text "XBUS19" at 65.786,17.78 h0.76 r90
  text "+VCCO3" at 68.326,17.78 h0.76 r90
  text "XBUS21" at 70.866,17.78 h0.76 r90
  text "XBUS23" at 73.406,17.78 h0.76 r90
  text "XBUS25" at 88.692,17.78 h0.76 r90
  text "XBUS27" at 91.232,17.78 h0.76 r90
  text "XBUS29" at 93.772,17.78 h0.76 r90
  text "XBUS31" at 96.312,17.78 h0.76 r90
  text "XBUS33" at 98.852,17.78 h0.76 r90
  text "XBUS35" at 101.392,17.78 h0.76 r90
  text "XBUS37" at 103.932,17.78 h0.76 r90
  text "+VCCO2" at 106.472,17.78 h0.76 r90
  text "XBUS39" at 109.012,17.78 h0.76 r90
  text "XBUS41" at 111.552,17.78 h0.76 r90
  text "XBUS43" at 114.092,17.78 h0.76 r90
  text "XBUS45" at 116.632,17.78 h0.76 r90
  text "XBUS47" at 119.172,17.78 h0.76 r90
  text "XBUS49" at 121.712,17.78 h0.76 r90
  text "XBUS51" at 124.252,17.78 h0.76 r90
  text "XBUS53" at 126.792,17.78 h0.76 r90
  text "XBUS55" at 129.332,17.78 h0.76 r90
  text "XBUS57" at 131.872,17.78 h0.76 r90
  text "X_CLK1" at 134.412,17.78 h0.76 r90
  text "X_CLK2" at 136.952,17.78 h0.76 r90
  text "DGND" at 40.386,8.128 h0.76 r90
  text "DGND" at 68.326,8.128 h0.76 r90
  text "DGND" at 106.472,8.128 h0.76 r90
  text "DGND" at 134.412,8.128 h0.76 r90
  text "DGND" at 136.952,8.128 h0.76 r90
  text "X_TDO" at 32.766,7.366 h0.76 r90
  text "XBUS0" at 42.926,7.366 h0.76 r90
  text "XBUS2" at 45.466,7.366 h0.76 r90
  text "XBUS4" at 48.006,7.366 h0.76 r90
  text "XBUS6" at 50.546,7.366 h0.76 r90
  text "XBUS8" at 53.086,7.366 h0.76 r90
  text "XBUS10" at 55.626,6.731 h0.76 r90
  text "XBUS12" at 58.166,6.731 h0.76 r90
  text "XBUS14" at 60.706,6.731 h0.76 r90
  text "XBUS16" at 63.246,6.731 h0.76 r90
  text "XBUS18" at 65.786,6.731 h0.76 r90
  text "XBUS20" at 70.866,6.604 h0.76 r90
  text "XBUS22" at 73.406,6.604 h0.76 r90
  text "XBUS24" at 88.692,6.604 h0.76 r90
  text "XBUS26" at 91.232,6.604 h0.76 r90
  text "XBUS28" at 93.772,6.604 h0.76 r90
  text "XBUS30" at 96.312,6.604 h0.76 r90
  text "XBUS32" at 98.852,6.604 h0.76 r90
  text "XBUS34" at 101.392,6.604 h0.76 r90
  text "XBUS36" at 103.932,6.604 h0.76 r90
  text "XBUS38" at 109.012,6.604 h0.76 r90
  text "XBUS40" at 111.552,6.604 h0.76 r90
  text "XBUS42" at 114.092,6.604 h0.76 r90
  text "XBUS44" at 116.632,6.604 h0.76 r90
  text "XBUS46" at 119.172,6.604 h0.76 r90
  text "XBUS48" at 121.712,6.604 h0.76 r90
  text "XBUS50" at 124.252,6.604 h0.76 r90
  text "XBUS52" at 126.792,6.604 h0.76 r90
  text "XBUS54" at 129.332,6.604 h0.76 r90
  text "XBUS56" at 131.872,6.604 h0.76 r90
  text "+3.3VDD" at 25.146,5.969 h0.76 r90
  text "+3.3VDD" at 27.686,5.969 h0.76 r90
  text "+3.3VDD" at 30.226,5.969 h0.76 r90
Mechanical 2:
  the board outline again, w0.203

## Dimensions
0,0 to 150,0 on Mechanical 1
0,0 to 0,100 on Mechanical 1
